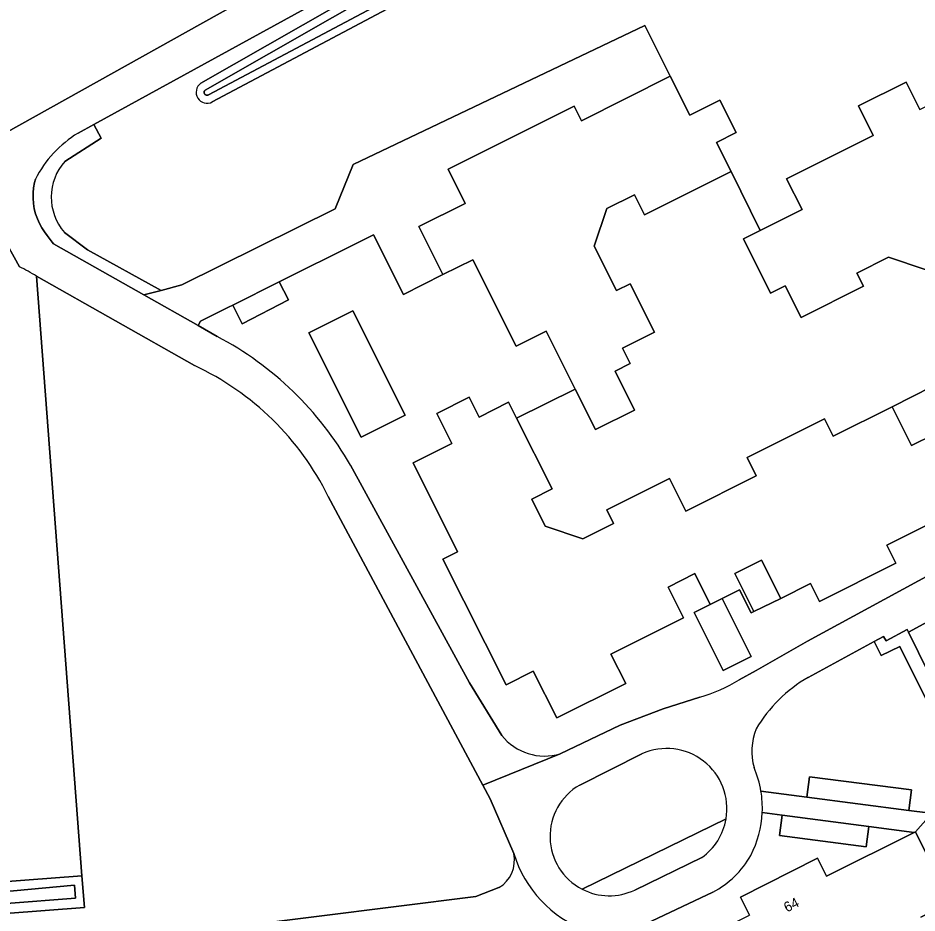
# Model space of a CAD drawing. Extents: x 158132 to 159664, y 385256 to 387218.
# Drawn here: x 158692.9 to 158782.6, y 386531.1 to 386620.5 of the extents above; entities that cross this region are included whole.
import ezdxf

# ---------------------------------------------------------------- set-up
doc = ezdxf.new("R2010")
doc.units = 0
for name, color, linetype in [('IMGEO_Erf', 7, 'Continuous'), ('IMGEO_Gemengd_bos', 7, 'Continuous'), ('IMGEO_Groenvoorziening', 7, 'Continuous'), ('IMGEO_Oever', 7, 'Continuous'), ('IMGEO_Pand', 7, 'Continuous'), ('IMGEO_Pand_nummerreeks', 7, 'Continuous'), ('IMGEO_Rijbaan_lokaal_gesloten', 7, 'Continuous'), ('IMGEO_Rijbaan_lokaal_open', 7, 'Continuous'), ('IMGEO_Voetpad_open', 7, 'Continuous'), ('IMGEO_Waterloop', 7, 'Continuous')]:
    doc.layers.add(name, color=color, linetype=linetype)

msp = doc.modelspace()

# ---------------------------------------------------------------- linework, layer by layer
at = {"layer": 'IMGEO_Erf'}
msp.add_lwpolyline([(158783.446, 386595.417), (158779.794, 386596.63), (158776.631, 386595.045), (158777.288, 386593.734), (158771.068, 386590.616), (158769.477, 386593.788), (158768.012, 386593.054), (158765.303, 386598.458), (158766.985, 386599.301), (158764.077, 386605.193), (158755.425, 386600.856), (158754.419, 386602.864), (158751.667, 386601.485), (158750.422, 386597.738), (158752.647, 386593.3), (158754.002, 386593.98), (158756.42, 386589.156), (158753.229, 386587.557), (158753.997, 386586.025), (158752.491, 386585.27), (158754.443, 386581.374), (158750.54, 386579.418), (158748.523, 386583.441), (158742.656, 386580.568), (158746.202, 386573.493), (158744.169, 386572.474), (158745.525, 386569.769), (158749.283, 386568.52), (158752.344, 386570.055), (158751.673, 386571.394), (158757.929, 386574.53), (158759.555, 386571.287), (158766.582, 386574.81), (158765.674, 386576.622), (158773.386, 386580.488), (158774.253, 386578.759), (158780.137, 386581.708), (158786.179, 386584.762)], dxfattribs=at)
msp.add_lwpolyline([(158796.955, 386563.379), (158797.349, 386562.596), (158798.629, 386563.238), (158797.571, 386565.346), (158803.578, 386568.362), (158807.498, 386560.555), (158811.338, 386562.479), (158808.121, 386572.96), (158806.237, 386572.518), (158781.776, 386559.201), (158784.771, 386553.097), (158786.616, 386554.023), (158784.946, 386557.35)], close=True, dxfattribs=at)
at = {"layer": 'IMGEO_Gemengd_bos'}
for points in [[(158710.503, 386585.816), (158694.746, 386594.725), (158699.275, 386534.87), (158699.517, 386531.694), (158557.249, 386520.848), (158552.808, 386577.121)], [(158742.38, 386537.071), (158740.024, 386542.527), (158739.279, 386543.919), (158723.865, 386572.731)], [(158406.579, 386559.501), (158407.365, 386554.435), (158412.576, 386546.234), (158416.913, 386541.171), (158442.575, 386509.712), (158448.358, 386503.022), (158452.614, 386500), (158453.96, 386499.044), (158456.49, 386498.14), (158462.815, 386498.14), (158466.249, 386498.502), (158477.427, 386500), (158500, 386502.833), (158738.601, 386532.775), (158740.897, 386533.672)], [(158824.465, 386529.474), (158820.639, 386532.177), (158815.114, 386550.18), (158813.721, 386549.753), (158805.546, 386545.648), (158808.477, 386539.811), (158802.716, 386536.919), (158798.895, 386544.53), (158796.049, 386543.101), (158792.172, 386550.824), (158789.017, 386549.24), (158788.025, 386551.216), (158784.943, 386549.67), (158780.903, 386557.764), (158779.062, 386556.845), (158778.358, 386558.256), (158771.759, 386554.672)], [(158767.055, 386543.309), (158771.623, 386542.716), (158771.888, 386544.755), (158782.073, 386543.432), (158781.809, 386541.393), (158783.697, 386541.148), (158783.805, 386541.134), (158783.744, 386540.665), (158782.467, 386539.253), (158785.99, 386532.235), (158783.014, 386530.741)]]:
    msp.add_lwpolyline(points, dxfattribs=at)
for centre, radius, start, end in [((158698.598, 386560.294), 28.162, 26.20712, 64.99304), ((158778.938, 386542.254), 14.344, 120.03352, 149.55631), ((158772.172, 386547.283), 6.031, 158.20959, 195.55585), ((158756.885, 386541.599), 10.313, 9.54335, 23.22521), ((158739.295, 386536.394), 3.158, 300.47361, 12.38264)]:
    msp.add_arc(centre, radius, start, end, dxfattribs=at)
at = {"layer": 'IMGEO_Groenvoorziening'}
for points in [[(158794.1, 386619.619), (158790.126, 386632.999), (158783.46, 386655.442), (158780.585, 386653.864), (158700.45, 386609.881), (158701.193, 386608.526), (158697.578, 386606.208)], [(158711.143, 386614.003), (158768.417, 386646.713), (158777.615, 386650.826), (158779.354, 386650.561), (158779.424, 386649.222), (158771.294, 386643.991), (158749.982, 386632.179)], [(158749.982, 386632.179), (158712.291, 386612.138)], [(158691.557, 386608.98), (158720.52, 386625.209)], [(158697.524, 386599.116), (158699.847, 386597.382), (158707.175, 386593.317), (158709.262, 386593.875), (158724.566, 386601.459), (158726.344, 386605.893), (158755.46, 386619.789), (158758.006, 386614.713), (158759.957, 386610.823), (158762.957, 386612.327), (158764.583, 386609.083), (158762.62, 386608.099), (158764.077, 386605.193), (158766.985, 386599.301), (158771.157, 386601.392), (158769.614, 386604.471), (158778.248, 386608.799), (158776.776, 386611.736), (158781.54, 386614.124), (158782.907, 386611.398), (158788.855, 386614.38), (158794.1, 386619.619)], [(158787.858, 386571.997), (158779.623, 386567.869), (158780.526, 386566.067), (158772.901, 386562.245), (158771.995, 386564.052), (158769.029, 386562.566), (158766.354, 386561.256), (158766.075, 386561.116), (158764.914, 386563.432), (158763.176, 386562.561), (158766.08, 386556.768), (158763.278, 386555.364), (158760.375, 386561.157), (158761.985, 386561.964), (158760.447, 386565.032), (158757.787, 386563.698), (158759.324, 386560.631), (158752.084, 386557.001), (158753.553, 386554.071), (158746.666, 386550.618), (158744.327, 386555.285), (158741.606, 386553.922), (158735.308, 386566.485), (158736.78, 386567.223), (158732.33, 386576.1), (158736.203, 386578.041), (158734.705, 386581.029), (158737.935, 386582.649), (158738.924, 386580.676), (158741.863, 386582.149), (158742.656, 386580.568), (158748.523, 386583.441), (158745.619, 386589.235), (158742.628, 386587.736), (158738.292, 386596.387), (158735.313, 386594.894), (158731.365, 386592.915), (158728.388, 386598.873), (158726.711, 386598.035), (158718.963, 386594.163), (158719.896, 386592.365), (158715.281, 386589.971), (158714.979, 386590.565), (158714.327, 386591.846), (158713.905, 386591.635), (158711.113, 386590.24), (158710.864, 386589.801), (158712.786, 386588.712)], [(158693.036, 386595.681), (158691.823, 386597.918)], [(158555.398, 386577.39), (158560.931, 386524.324), (158699.275, 386534.87), (158694.746, 386594.725)], [(158786.179, 386584.762), (158780.137, 386581.708), (158782.086, 386577.821), (158784.365, 386578.963)], [(158764.888, 386554.437), (158766.579, 386555.347), (158771.698, 386558.283), (158806.101, 386577.002)], [(158726.073, 386575.857), (158737.974, 386554.129), (158741.174, 386548.87)], [(158747.019, 386547.038), (158753.004, 386549.89), (158757.281, 386551.535), (158760.968, 386552.713)], [(158761.215, 386525.612), (158760.03, 386527.972), (158762.987, 386529.456), (158765.91, 386530.923), (158764.998, 386532.738), (158772.701, 386536.605), (158773.605, 386534.804), (158782.357, 386539.198), (158777.813, 386539.788), (158777.549, 386537.761), (158768.898, 386538.884), (158769.162, 386540.911), (158767.184, 386541.168)], [(158762.252, 386533.225), (158755.575, 386530.073)]]:
    msp.add_lwpolyline(points, dxfattribs=at)
msp.add_lwpolyline([(158727.144, 386578.665), (158721.923, 386589.083), (158726.313, 386591.284), (158731.534, 386580.865)], close=True, dxfattribs=at)
for centre, radius, start, end in [((158711.772, 386613.104), 1.097, 124.98512, 298.2436), ((158701.578, 386602.631), 5.366, 138.19508, 220.93241), ((158687.11, 386583.074), 13.931, 56.75989, 64.82411), ((158697.426, 386559.541), 32.968, 29.6632, 62.23027), ((158756.694, 386567.75), 15.633, 285.86734, 301.61205), ((158745.468, 386552.331), 5.516, 218.86853, 286.32633), ((158756.967, 386541.628), 10.227, 332.45397, 357.42445), ((158757.949, 386541.441), 9.275, 297.64074, 330.66879)]:
    msp.add_arc(centre, radius, start, end, dxfattribs=at)
at = {"layer": 'IMGEO_Oever'}
for points in [[(158749.982, 386632.179), (158771.294, 386643.991), (158779.424, 386649.222), (158779.354, 386650.561), (158777.615, 386650.826), (158768.417, 386646.713), (158711.143, 386614.003)], [(158749.6, 386632.883), (158711.913, 386612.844), (158711.89, 386612.833), (158711.866, 386612.824), (158711.841, 386612.817), (158711.816, 386612.812), (158711.791, 386612.809), (158711.765, 386612.808), (158711.74, 386612.81), (158711.714, 386612.814), (158711.689, 386612.82), (158711.665, 386612.828), (158711.642, 386612.838), (158711.619, 386612.851), (158711.598, 386612.865), (158711.578, 386612.881), (158711.559, 386612.898), (158711.542, 386612.917), (158711.527, 386612.938), (158711.513, 386612.96), (158711.502, 386612.983), (158711.492, 386613.007), (158711.485, 386613.031), (158711.48, 386613.056), (158711.477, 386613.082), (158711.476, 386613.107), (158711.477, 386613.133), (158711.481, 386613.158), (158711.487, 386613.183), (158711.494, 386613.207), (158711.504, 386613.231), (158711.516, 386613.254), (158711.53, 386613.275), (158711.546, 386613.296), (158711.563, 386613.314), (158711.582, 386613.332), (158768.78, 386645.998)], [(158712.291, 386612.138), (158749.982, 386632.179)]]:
    msp.add_lwpolyline(points, dxfattribs=at)
for points in [[(158699.517, 386531.694), (158699.275, 386534.87), (158560.931, 386524.324), (158555.398, 386577.39), (158554.967, 386582.608), (158552.53, 386582.407), (158552.392, 386582.396), (158552.808, 386577.121), (158557.249, 386520.848)], [(158553.097, 386581.977), (158554.238, 386582.062), (158554.539, 386578.892), (158559.851, 386523.083), (158621.584, 386527.435), (158637.997, 386528.755), (158675.25, 386531.751), (158698.529, 386533.91), (158698.648, 386532.633), (158664.152, 386529.965), (158634.366, 386527.662), (158583.718, 386523.548), (158559.053, 386521.763), (158558.315, 386529.529), (158553.165, 386581.296)]]:
    msp.add_lwpolyline(points, close=True, dxfattribs=at)
msp.add_arc((158711.772, 386613.104), 1.097, 124.98512, 298.2436, dxfattribs=at)
at = {"layer": 'IMGEO_Pand'}
for points in [[(158754.002, 386593.98), (158752.647, 386593.3), (158750.422, 386597.738), (158751.667, 386601.485), (158754.419, 386602.864), (158755.425, 386600.856), (158764.077, 386605.193), (158762.62, 386608.099), (158764.583, 386609.083), (158762.957, 386612.327), (158759.957, 386610.823), (158758.006, 386614.713), (158749.132, 386610.265), (158748.402, 386611.722), (158735.829, 386605.42), (158737.536, 386602.014), (158732.907, 386599.694), (158735.313, 386594.894), (158738.292, 386596.387), (158742.628, 386587.736), (158745.619, 386589.235), (158748.523, 386583.441), (158750.54, 386579.418), (158754.443, 386581.374), (158752.491, 386585.27), (158753.997, 386586.025), (158753.229, 386587.557), (158756.42, 386589.156)], [(158727.144, 386578.665), (158731.534, 386580.865), (158726.313, 386591.284), (158721.923, 386589.083)], [(158763.176, 386562.561), (158761.985, 386561.964), (158760.375, 386561.157), (158763.278, 386555.364), (158766.08, 386556.768)]]:
    msp.add_lwpolyline(points, close=True, dxfattribs=at)
for points in [[(158782.907, 386611.398), (158781.54, 386614.124), (158776.776, 386611.736), (158778.248, 386608.799), (158769.614, 386604.471), (158771.157, 386601.392), (158766.985, 386599.301), (158765.303, 386598.458), (158768.012, 386593.054), (158769.477, 386593.788), (158771.068, 386590.616), (158777.288, 386593.734), (158776.631, 386595.045), (158779.794, 386596.63), (158783.446, 386595.417)], [(158784.365, 386578.963), (158782.086, 386577.821), (158780.137, 386581.708), (158774.253, 386578.759), (158773.386, 386580.488), (158765.674, 386576.622), (158766.582, 386574.81), (158759.555, 386571.287), (158757.929, 386574.53), (158751.673, 386571.394), (158752.344, 386570.055), (158749.283, 386568.52), (158745.525, 386569.769), (158744.169, 386572.474), (158746.202, 386573.493), (158742.656, 386580.568), (158741.863, 386582.149), (158738.924, 386580.676), (158737.935, 386582.649), (158734.705, 386581.029), (158736.203, 386578.041), (158732.33, 386576.1), (158736.78, 386567.223), (158735.308, 386566.485), (158741.606, 386553.922), (158744.327, 386555.285), (158746.666, 386550.618), (158753.553, 386554.071), (158752.084, 386557.001), (158759.324, 386560.631), (158757.787, 386563.698), (158760.447, 386565.032), (158761.985, 386561.964), (158763.176, 386562.561), (158764.914, 386563.432), (158766.075, 386561.116), (158766.354, 386561.256), (158764.459, 386565.035), (158767.122, 386566.37), (158769.029, 386562.566), (158771.995, 386564.052), (158772.901, 386562.245), (158780.526, 386566.067), (158779.623, 386567.869), (158787.858, 386571.997)], [(158783.014, 386530.741), (158785.99, 386532.235), (158782.467, 386539.253), (158782.357, 386539.198), (158773.605, 386534.804), (158772.701, 386536.605), (158764.998, 386532.738), (158765.91, 386530.923)]]:
    msp.add_lwpolyline(points, dxfattribs=at)
at = {"layer": 'IMGEO_Rijbaan_lokaal_gesloten'}
for points in [[(158781.06, 386658.156), (158750.956, 386641.69), (158750.874, 386641.615), (158743.018, 386637.303), (158742.852, 386637.2), (158742.68, 386637.109), (158738.627, 386634.99), (158732.149, 386631.604), (158728.617, 386629.757), (158720.52, 386625.209), (158691.557, 386608.98)], [(158698.887, 386609.023), (158700.45, 386609.881), (158780.585, 386653.864), (158783.46, 386655.442), (158785.025, 386656.561), (158786.969, 386657.085), (158789.224, 386650.313), (158792.532, 386639.18), (158793.03, 386637.504), (158797.726, 386621.697), (158798.47, 386619.193), (158802.896, 386604.296), (158803.453, 386602.422), (158806.62, 386591.762), (158808.974, 386584.017), (158809.09, 386583.794), (158812.129, 386571.242), (158812.863, 386568.958), (158814.558, 386563.685), (158815.143, 386561.833), (158816.103, 386558.798), (158816.597, 386557.237), (158820.951, 386543.469), (158822.483, 386539.207)], [(158712.786, 386588.712), (158710.864, 386589.801), (158705.467, 386592.861), (158696.439, 386597.978), (158696.312, 386598.13), (158695.796, 386598.788), (158695.528, 386599.17), (158695.275, 386599.571), (158695.04, 386600.004), (158694.829, 386600.472), (158694.655, 386600.968), (158694.525, 386601.48), (158694.439, 386601.999), (158694.397, 386602.523), (158694.4, 386603.049), (158694.448, 386603.574), (158694.541, 386604.088), (158694.631, 386604.425)], [(158691.823, 386597.918), (158693.036, 386595.681)], [(158694.746, 386594.725), (158710.503, 386585.816)], [(158806.101, 386577.002), (158771.698, 386558.283), (158766.579, 386555.347), (158764.888, 386554.437)], [(158741.174, 386548.87), (158737.974, 386554.129), (158726.073, 386575.857)], [(158771.759, 386554.672), (158778.358, 386558.256), (158779.295, 386558.765), (158779.552, 386558.318), (158781.645, 386559.468), (158781.776, 386559.201), (158806.237, 386572.518), (158808.121, 386572.96), (158809.947, 386573.401)], [(158723.865, 386572.731), (158739.279, 386543.919), (158747.019, 386547.038)], [(158740.897, 386533.672), (158738.601, 386532.775), (158500, 386502.833), (158477.427, 386500), (158466.249, 386498.502), (158462.815, 386498.14), (158456.49, 386498.14), (158453.96, 386499.044), (158452.614, 386500), (158448.358, 386503.022), (158442.575, 386509.712), (158416.913, 386541.171), (158412.576, 386546.234), (158407.365, 386554.435), (158406.579, 386559.501)], [(158760.968, 386552.713), (158757.281, 386551.535), (158753.004, 386549.89), (158747.019, 386547.038), (158739.279, 386543.919), (158740.024, 386542.527), (158742.38, 386537.071)], [(158748.96, 386543.916), (158755.177, 386547.033)], [(158761.144, 386536.672), (158754.453, 386533.431)], [(158755.575, 386530.073), (158762.252, 386533.225)]]:
    msp.add_lwpolyline(points, dxfattribs=at)
for centre, radius, start, end in [((158704.825, 386599.258), 11.429, 121.30392, 153.12017), ((158687.11, 386583.074), 13.931, 56.75989, 64.82411), ((158697.426, 386559.541), 32.968, 29.6632, 62.23027), ((158698.598, 386560.294), 28.162, 26.20712, 64.99304), ((158756.694, 386567.75), 15.633, 285.86734, 301.61205), ((158778.938, 386542.254), 14.344, 120.03352, 149.55631), ((158772.172, 386547.283), 6.031, 158.20959, 195.55585), ((158745.468, 386552.331), 5.516, 218.86853, 286.32633), ((158757.65, 386541.559), 6.007, 350.14192, 114.31354), ((158756.885, 386541.599), 10.313, 9.54335, 23.22521), ((158751.919, 386538.785), 5.923, 119.96824, 242.65546), ((158756.744, 386541.613), 10.45, 357.55757, 9.33849), ((158756.967, 386541.628), 10.227, 332.45397, 357.42445), ((158757.646, 386541.562), 6.012, 305.57637, 350.11965), ((158739.295, 386536.394), 3.158, 300.47361, 12.38264), ((158753.893, 386540.663), 12.061, 197.32877, 249.24816), ((158753.893, 386540.663), 12.061, 197.32877, 249.24816), ((158757.949, 386541.441), 9.275, 297.64074, 330.66879), ((158751.918, 386538.782), 5.921, 242.6499, 295.34413)]:
    msp.add_arc(centre, radius, start, end, dxfattribs=at)
at = {"layer": 'IMGEO_Rijbaan_lokaal_open'}
for points in [[(158763.569, 386540.53), (158749.198, 386533.523)], [(158754.453, 386533.431), (158761.144, 386536.672)]]:
    msp.add_lwpolyline(points, dxfattribs=at)
for centre, radius, start, end in [((158757.646, 386541.562), 6.012, 305.57637, 350.11965), ((158751.918, 386538.782), 5.921, 242.6499, 295.34413)]:
    msp.add_arc(centre, radius, start, end, dxfattribs=at)
at = {"layer": 'IMGEO_Voetpad_open'}
for points in [[(158737.536, 386602.014), (158735.829, 386605.42), (158748.402, 386611.722), (158749.132, 386610.265), (158758.006, 386614.713), (158755.46, 386619.789), (158726.344, 386605.893), (158724.566, 386601.459), (158709.262, 386593.875), (158707.175, 386593.317), (158705.467, 386592.861), (158710.864, 386589.801), (158711.113, 386590.24), (158713.905, 386591.635), (158714.327, 386591.846), (158718.963, 386594.163), (158726.711, 386598.035), (158728.388, 386598.873), (158731.365, 386592.915), (158735.313, 386594.894), (158732.907, 386599.694)], [(158718.963, 386594.163), (158714.327, 386591.846), (158714.979, 386590.565), (158715.281, 386589.971), (158719.896, 386592.365)], [(158769.029, 386562.566), (158767.122, 386566.37), (158764.459, 386565.035), (158766.354, 386561.256)], [(158786.616, 386554.023), (158784.771, 386553.097), (158781.776, 386559.201), (158781.645, 386559.468), (158779.552, 386558.318), (158779.295, 386558.765), (158778.358, 386558.256), (158779.062, 386556.845), (158780.903, 386557.764), (158784.943, 386549.67), (158788.025, 386551.216)], [(158771.623, 386542.716), (158781.809, 386541.393), (158782.073, 386543.432), (158771.888, 386544.755)], [(158777.813, 386539.788), (158769.162, 386540.911), (158768.898, 386538.884), (158777.549, 386537.761)]]:
    msp.add_lwpolyline(points, close=True, dxfattribs=at)
for points in [[(158697.578, 386606.208), (158701.193, 386608.526), (158700.45, 386609.881), (158698.887, 386609.023)], [(158694.631, 386604.425), (158694.541, 386604.088), (158694.448, 386603.574), (158694.4, 386603.049), (158694.397, 386602.523), (158694.439, 386601.999), (158694.525, 386601.48), (158694.655, 386600.968), (158694.829, 386600.472), (158695.04, 386600.004), (158695.275, 386599.571), (158695.528, 386599.17), (158695.796, 386598.788), (158696.312, 386598.13), (158696.439, 386597.978), (158705.467, 386592.861), (158707.175, 386593.317), (158699.847, 386597.382), (158697.524, 386599.116)], [(158755.177, 386547.033), (158748.96, 386543.916)], [(158771.623, 386542.716), (158767.055, 386543.309)], [(158767.184, 386541.168), (158769.162, 386540.911), (158777.813, 386539.788), (158782.357, 386539.198), (158782.467, 386539.253), (158783.744, 386540.665), (158783.805, 386541.134), (158783.697, 386541.148), (158781.809, 386541.393), (158771.623, 386542.716)], [(158749.198, 386533.523), (158763.569, 386540.53)]]:
    msp.add_lwpolyline(points, dxfattribs=at)
for centre, radius, start, end in [((158704.825, 386599.258), 11.429, 121.30392, 153.12017), ((158701.578, 386602.631), 5.366, 138.19508, 220.93241), ((158757.65, 386541.559), 6.007, 350.14192, 114.31354), ((158751.919, 386538.785), 5.923, 119.96824, 242.65546), ((158756.744, 386541.613), 10.45, 357.55757, 9.33849)]:
    msp.add_arc(centre, radius, start, end, dxfattribs=at)
at = {"layer": 'IMGEO_Waterloop'}
msp.add_lwpolyline([(158768.78, 386645.998), (158711.582, 386613.332), (158711.563, 386613.314), (158711.546, 386613.296), (158711.53, 386613.275), (158711.516, 386613.254), (158711.504, 386613.231), (158711.494, 386613.207), (158711.487, 386613.183), (158711.481, 386613.158), (158711.477, 386613.133), (158711.476, 386613.107), (158711.477, 386613.082), (158711.48, 386613.056), (158711.485, 386613.031), (158711.492, 386613.007), (158711.502, 386612.983), (158711.513, 386612.96), (158711.527, 386612.938), (158711.542, 386612.917), (158711.559, 386612.898), (158711.578, 386612.881), (158711.598, 386612.865), (158711.619, 386612.851), (158711.642, 386612.838), (158711.665, 386612.828), (158711.689, 386612.82), (158711.714, 386612.814), (158711.74, 386612.81), (158711.765, 386612.808), (158711.791, 386612.809), (158711.816, 386612.812), (158711.841, 386612.817), (158711.866, 386612.824), (158711.89, 386612.833), (158711.913, 386612.844), (158749.6, 386632.883)], dxfattribs=at)
msp.add_lwpolyline([(158553.097, 386581.977), (158553.165, 386581.296), (158558.315, 386529.529), (158559.053, 386521.763), (158583.718, 386523.548), (158634.366, 386527.662), (158664.152, 386529.965), (158698.648, 386532.633), (158698.529, 386533.91), (158675.25, 386531.751), (158637.997, 386528.755), (158621.584, 386527.435), (158559.851, 386523.083), (158554.539, 386578.892), (158554.238, 386582.062)], close=True, dxfattribs=at)

# ---------------------------------------------------------------- texts
at = {"layer": 'IMGEO_Pand_nummerreeks'}
msp.add_text('64', height=1, rotation=26.57951, dxfattribs=at).set_placement((158769.646, 386531.184))

doc.saveas('drawing.dxf')
